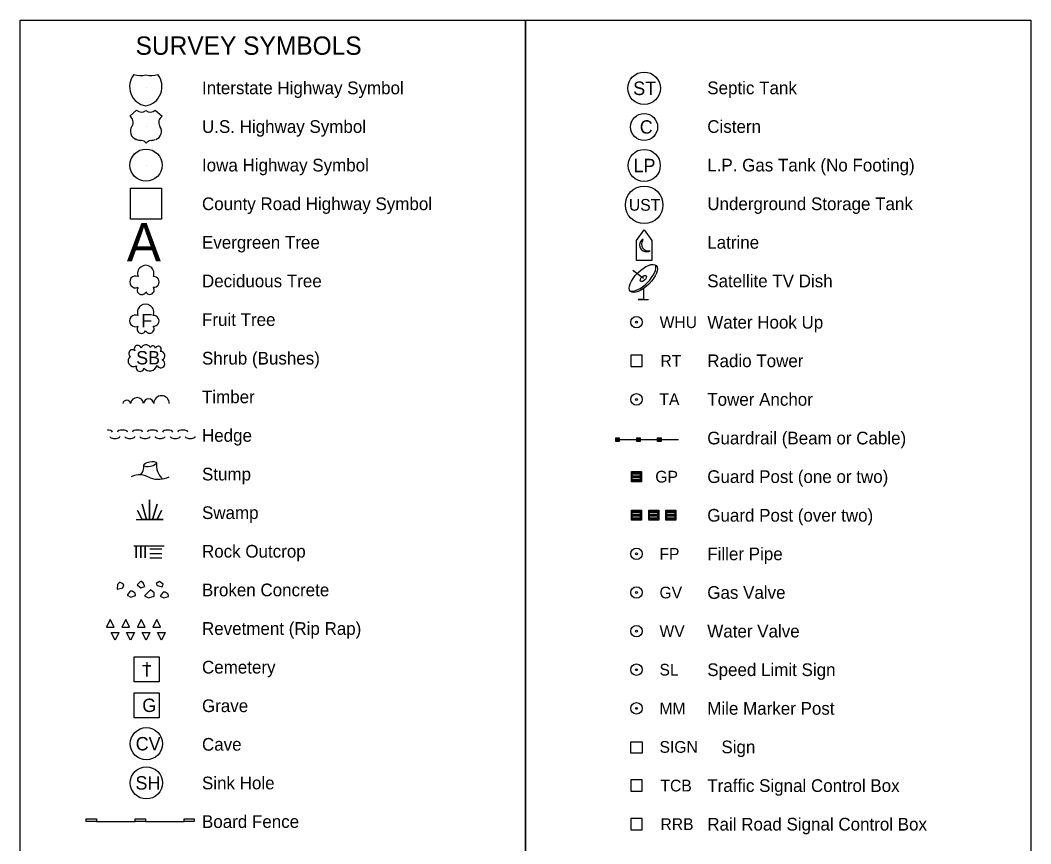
# Model space of a CAD drawing. Extents: x 6082259 to 6083454, y 5964102 to 5966092.
# Drawn here: x 6082259 to 6083454, y 5965119 to 5966092 of the extents above; entities that cross this region are included whole.
import ezdxf

# ---------------------------------------------------------------- set-up
doc = ezdxf.new("R2010")
doc.units = 0
for name, color, linetype in [('Default', 7, 'Continuous'), ('dsnCellElements', 7, 'Continuous'), ('SheetBorder', 7, 'Continuous'), ('Text', 7, 'Continuous')]:
    doc.layers.add(name, color=color, linetype=linetype)

msp = doc.modelspace()

# ---------------------------------------------------------------- linework, layer by layer
at = {"layer": 'Default'}
for points in [[(6082259, 5966092.2), (6082856.5, 5966092.2), (6082856.5, 5964102.2), (6082259, 5964102.2)], [(6082856.5, 5966092.2), (6083454, 5966092.2), (6083454, 5964102.2), (6082856.5, 5964102.2)]]:
    msp.add_lwpolyline(points, close=True, dxfattribs=at)
at = {"layer": 'dsnCellElements'}
for p, q in [((6082407.8, 5966012.2), (6082407.8, 5966012.2)), ((6082388.5, 5965978.8), (6082396.6, 5965986)), ((6082418.8, 5965985.9), (6082426.9, 5965978.7)), ((6082391, 5965966.7), (6082391.4, 5965967.3)), ((6082407.8, 5965966.5), (6082407.8, 5965966.5)), ((6082396.7, 5965951), (6082396, 5965951.3)), ((6082402.5, 5965950.1), (6082401.5, 5965950.1)), ((6082407.8, 5965920.9), (6082407.8, 5965920.9)), ((6082995.9, 5965786.9), (6082983.5, 5965796.2)), ((6082412.3, 5965467.3), (6082426.5, 5965467.3)), ((6082412.3, 5965462), (6082426.5, 5965462)), ((6082412.3, 5965456.6), (6082426.5, 5965456.6))]:
    msp.add_line(p, q, dxfattribs=at)
for points in [[(6082389.5, 5965893.5), (6082426, 5965893.5), (6082426, 5965857), (6082389.5, 5965857), (6082389.5, 5965893.5)], [(6082987.8, 5965808.3), (6082987.8, 5965831.8), (6082996.9, 5965844.5), (6083005.9, 5965831.8), (6083005.9, 5965808.3), (6082987.8, 5965808.3)], [(6082995.9, 5965774.5), (6082995.9, 5965762.1), (6082989.7, 5965762.1), (6083002.1, 5965762.1)], [(6082987.8, 5965682.8), (6082987.8, 5965682.8), (6082994.6, 5965682.8), (6082994.6, 5965696.4), (6082981, 5965696.4), (6082981, 5965682.8), (6082987.8, 5965682.8)], [(6082963.2, 5965594.3), (6082963.2, 5965598.4), (6082967.3, 5965598.4), (6082967.3, 5965594.3), (6082963.2, 5965594.3), (6082963.2, 5965595.7), (6082967.3, 5965595.7), (6082967.3, 5965597), (6082963.2, 5965597)], [(6082963.2, 5965596.4), (6083037.5, 5965596.4)], [(6082988, 5965594.3), (6082988, 5965598.4), (6082992.1, 5965598.4), (6082992.1, 5965594.3), (6082988, 5965594.3), (6082988, 5965595.7), (6082992.1, 5965595.7), (6082992.1, 5965597), (6082988, 5965597)], [(6083012.7, 5965594.3), (6083012.7, 5965598.4), (6083016.9, 5965598.4), (6083016.9, 5965594.3), (6083012.7, 5965594.3), (6083012.7, 5965595.7), (6083016.9, 5965595.7), (6083016.9, 5965597), (6083012.7, 5965597)], [(6082982.8, 5965547.7), (6082982.8, 5965557.6), (6082992.7, 5965557.6), (6082992.7, 5965547.7), (6082982.8, 5965547.7), (6082982.8, 5965549.7), (6082992.7, 5965549.7), (6082992.7, 5965551.7), (6082982.8, 5965551.7), (6082982.8, 5965553.7), (6082992.7, 5965553.7), (6082992.7, 5965555.6), (6082982.8, 5965555.6)], [(6082396, 5965502.1), (6082428.1, 5965502.1), (6082421, 5965502.1), (6082426.3, 5965512.8), (6082421, 5965502.1), (6082415.6, 5965502.1), (6082421, 5965520), (6082415.6, 5965502.1), (6082412.1, 5965502.1), (6082412.1, 5965525.3), (6082412.1, 5965502.1), (6082408.5, 5965502.1), (6082403.2, 5965520), (6082408.5, 5965502.1), (6082403.2, 5965502.1), (6082397.8, 5965512.8), (6082403.2, 5965502.1)], [(6082982.8, 5965502.1), (6082982.8, 5965512), (6082992.7, 5965512), (6082992.7, 5965502.1), (6082982.8, 5965502.1), (6082982.8, 5965504.1), (6082992.7, 5965504.1), (6082992.7, 5965506), (6082982.8, 5965506), (6082982.8, 5965508), (6082992.7, 5965508), (6082992.7, 5965510), (6082982.8, 5965510)], [(6083003.2, 5965502.1), (6083003.2, 5965512), (6083013.1, 5965512), (6083013.1, 5965502.1), (6083003.2, 5965502.1), (6083003.2, 5965504.1), (6083013.1, 5965504.1), (6083013.1, 5965506), (6083003.2, 5965506), (6083003.2, 5965508), (6083013.1, 5965508), (6083013.1, 5965510), (6083003.2, 5965510)], [(6083023.5, 5965502.1), (6083023.5, 5965512), (6083033.4, 5965512), (6083033.4, 5965502.1), (6083023.5, 5965502.1), (6083023.5, 5965504.1), (6083033.4, 5965504.1), (6083033.4, 5965506), (6083023.5, 5965506), (6083023.5, 5965508), (6083033.4, 5965508), (6083033.4, 5965510), (6083023.5, 5965510)], [(6082393.5, 5965470.9), (6082396.2, 5965470.9), (6082396.2, 5965456.6), (6082396.2, 5965470.9), (6082401.6, 5965470.9), (6082401.6, 5965456.6), (6082401.6, 5965470.9), (6082406.9, 5965470.9), (6082406.9, 5965456.6), (6082406.9, 5965470.9), (6082429.2, 5965470.9)], [(6082361, 5965374.6), (6082370.2, 5965374.6), (6082365.6, 5965383.8), (6082361, 5965374.6)], [(6082379.3, 5965374.6), (6082388.4, 5965374.6), (6082383.9, 5965383.8), (6082379.3, 5965374.6)], [(6082397.6, 5965374.6), (6082406.7, 5965374.6), (6082402.1, 5965383.8), (6082397.6, 5965374.6)], [(6082415.8, 5965374.6), (6082424.9, 5965374.6), (6082420.4, 5965383.8), (6082415.8, 5965374.6)], [(6082366.7, 5965368.6), (6082375.8, 5965368.6), (6082371.2, 5965359.5), (6082366.7, 5965368.6)], [(6082384.9, 5965368.6), (6082394.1, 5965368.6), (6082389.5, 5965359.5), (6082384.9, 5965368.6)], [(6082403.2, 5965368.6), (6082412.3, 5965368.6), (6082407.8, 5965359.5), (6082403.2, 5965368.6)], [(6082421.5, 5965368.6), (6082430.6, 5965368.6), (6082426, 5965359.5), (6082421.5, 5965368.6)], [(6082393.8, 5965310.2), (6082393.8, 5965339.7), (6082423.4, 5965339.7), (6082423.4, 5965310.2), (6082393.8, 5965310.2)], [(6082408.6, 5965333.3), (6082408.6, 5965316.6), (6082408.6, 5965328.9), (6082413.5, 5965328.9), (6082403.7, 5965328.9)], [(6082987.8, 5965180.8), (6082987.8, 5965180.8), (6082994.6, 5965180.8), (6082994.6, 5965194.3), (6082981, 5965194.3), (6082981, 5965180.8), (6082987.8, 5965180.8)], [(6082349.4, 5965145), (6082395, 5965145)], [(6082407.2, 5965145), (6082452.8, 5965145)], [(6082464.9, 5965145), (6082464.9, 5965145)], [(6082987.8, 5965135.1), (6082987.8, 5965135.1), (6082994.6, 5965135.1), (6082994.6, 5965148.7), (6082981, 5965148.7), (6082981, 5965135.1), (6082987.8, 5965135.1)]]:
    msp.add_lwpolyline(points, dxfattribs=at)
for points in [[(6082981.8, 5965546.7), (6082981.8, 5965558.6), (6082993.7, 5965558.6), (6082993.7, 5965546.7)], [(6082981.8, 5965501.1), (6082981.8, 5965513), (6082993.7, 5965513), (6082993.7, 5965501.1)], [(6083002.2, 5965501.1), (6083002.2, 5965513), (6083014.1, 5965513), (6083014.1, 5965501.1)], [(6083022.5, 5965501.1), (6083022.5, 5965513), (6083034.4, 5965513), (6083034.4, 5965501.1)], [(6082401.7, 5965429), (6082397.3, 5965424.9), (6082401.5, 5965421.3), (6082406.4, 5965422.8), (6082404.3, 5965427.2)], [(6082423.7, 5965428.6), (6082419.9, 5965426.3), (6082421.1, 5965424.2), (6082427.1, 5965422.6), (6082427.9, 5965425.5)], [(6082376.8, 5965427.8), (6082374.2, 5965425.4), (6082373.7, 5965419.7), (6082380.2, 5965421.3), (6082381.5, 5965424.9), (6082379.7, 5965426.2)], [(6082389.2, 5965417.2), (6082385.6, 5965412.5), (6082389.8, 5965410.4), (6082395.5, 5965412.3), (6082394.9, 5965415.1), (6082391.3, 5965417.2)], [(6082413.2, 5965419), (6082406, 5965411.8), (6082410.9, 5965409.4), (6082417.4, 5965411.3), (6082417.6, 5965415.4)], [(6082428.2, 5965416), (6082424.6, 5965411.4), (6082428.7, 5965409.3), (6082434.4, 5965411.1), (6082433.9, 5965413.9), (6082430.3, 5965416)], [(6082393.7, 5965267.5), (6082393.7, 5965297.2), (6082423.5, 5965297.2), (6082423.5, 5965267.5)], [(6082981, 5965225.7), (6082981, 5965239.2), (6082994.6, 5965239.2), (6082994.6, 5965225.7)], [(6082337.2, 5965145), (6082337.2, 5965148.4), (6082349.4, 5965148.4), (6082349.4, 5965145)], [(6082395, 5965145), (6082395, 5965148.4), (6082407.2, 5965148.4), (6082407.2, 5965145)], [(6082452.8, 5965145), (6082452.8, 5965148.4), (6082464.9, 5965148.4), (6082464.9, 5965145)]]:
    msp.add_lwpolyline(points, close=True, dxfattribs=at)
for centre, radius in [((6082996.8, 5965966), 16), ((6082407.8, 5965920.9), 19), ((6082996.9, 5965920.5), 19), ((6082996.9, 5965873.9), 22.2), ((6082987.8, 5965735.2), 6.79), ((6082987.8, 5965735.2), 1.13), ((6082987.8, 5965644), 6.79), ((6082987.8, 5965644), 1.13), ((6082987.8, 5965461.4), 6.79), ((6082987.8, 5965461.4), 1.13), ((6082987.8, 5965415.8), 6.79), ((6082987.8, 5965415.8), 1.13), ((6082987.8, 5965370.1), 6.79), ((6082987.8, 5965370.1), 1.13), ((6082987.8, 5965324.5), 6.79), ((6082987.8, 5965324.5), 1.13), ((6082987.8, 5965278.8), 6.79), ((6082987.8, 5965278.8), 1.13), ((6082408.2, 5965237), 19), ((6082408.2, 5965190.7), 19)]:
    msp.add_circle(centre, radius, dxfattribs=at)
for centre, radius, start, end in [((6082411.4, 5966013.6), 23, 141.2897, 260.377), ((6082401.1, 5966050), 23.3, 250.8344, 286.0898), ((6082414, 5966050), 23.3, 253.9102, 289.1613), ((6082403.7, 5966013.6), 23, 279.623, 38.7204), ((6082414, 5966050), 23.3, 289.1818, 289.185), ((6082384.1, 5965971.6), 8.46, 328.1178, 58.4185), ((6082402.4, 5965992.1), 8.46, 226.652, 308.6604), ((6082413, 5965992.1), 8.46, 230.5703, 313.348), ((6082431.3, 5965971.5), 8.46, 121.5815, 211.8822), ((6082399.6, 5965961), 10.3, 145.8972, 250.3585), ((6082415.8, 5965960.9), 10.3, 289.6415, 34.1028), ((6082403.5, 5965974.1), 24.1, 253.4797, 265.7777), ((6082402.1, 5965943), 7.07, 33.6844, 87.4407), ((6082413.9, 5965942.9), 7.07, 95.8567, 146.3156), ((6082411.9, 5965974.1), 24.1, 274.6642, 286.5203), ((6082999.3, 5965826.4), 7.87, 116.2289, 304.7925), ((6083001.5, 5965827.5), 7.91, 142.8907, 286.2253), ((6082407.5, 5965792.7), 9.75, 338.2051, 201.7949), ((6082395.5, 5965782.8), 6.97, 65.4824, 294.5175), ((6082417, 5965782.8), 6.36, 265.9982, 94.0018), ((6082402.6, 5965773.2), 5.31, 142.7501, 335.3223), ((6082412.2, 5965773.4), 5.3, 206.5242, 35.4033), ((6082407.3, 5965746.8), 9.75, 338.2051, 201.7949), ((6082395.4, 5965736.8), 6.97, 65.4824, 294.5175), ((6082416.8, 5965736.8), 6.36, 265.9982, 94.0018), ((6082402.5, 5965727.3), 5.31, 142.7501, 335.3223), ((6082412.1, 5965727.4), 5.3, 206.5242, 35.4033), ((6082398.1, 5965703.7), 4.12, 10.5948, 214.3611), ((6082407.6, 5965703.1), 5.57, 22.6036, 165.7836), ((6082415.7, 5965704.1), 3.15, 0.4605, 158.7839), ((6082422.3, 5965703.3), 3.57, 311.3936, 166.4114), ((6082393.2, 5965689.4), 6.62, 125.8289, 299.2848), ((6082391.7, 5965698.3), 4.32, 45.3455, 236.8073), ((6082425, 5965695.5), 5.15, 290.9039, 94.3687), ((6082400.8, 5965681.8), 4.68, 157.0258, 349.7602), ((6082412.2, 5965686.7), 8.99, 220.0183, 343.6977), ((6082425.2, 5965686.2), 4.79, 204.8294, 69.8871), ((6082397.2, 5965638.4), 7.66, 5.6097, 174.3903), ((6082410.9, 5965638.4), 6.15, 6.8184, 173.1816), ((6082426.2, 5965639.2), 9.15, 0, 180), ((6082385, 5965638.5), 4.63, 8.8069, 171.1931), ((6082388.6, 5965565.5), 16.7, 319.4836, 1.8241), ((6082444, 5965567.1), 24, 175.4776, 225.2691), ((6082400.1, 5965530.5), 24.2, 58.6739, 113.6979), ((6082422.1, 5965578.6), 29, 251.1942, 296.4339)]:
    msp.add_arc(centre, radius, start, end, dxfattribs=at)
for centre, major_axis, ratio in [((6082995.9, 5965786.9), (-15.3, -15.3), 0.428571), ((6082995.9, 5965786.9), (-3.28, -3.28), 0.5), ((6082412.7, 5965567.5), (-7.43, -1.49), 0.385758)]:
    msp.add_ellipse(centre, major_axis=major_axis, ratio=ratio, dxfattribs=at)
for centre, major_axis, ratio, start_param, end_param in [((6082994.1, 5965788.6), (-15.3, -15.3), 0.428571, 0.159141, 2.993624), ((6082362.1, 5965605.4), (5.94, 0), 0.4, 0, 1.570796), ((6082379.9, 5965605.4), (-5.94, 0), 0.4, 4.712389, 6.283185), ((6082379.9, 5965605.4), (5.94, 0), 0.4, 0, 1.570796), ((6082397.7, 5965605.4), (-5.94, 0), 0.4, 4.712389, 6.283185), ((6082397.7, 5965605.4), (5.94, 0), 0.4, 0, 1.570796), ((6082415.5, 5965605.4), (-5.94, 0), 0.4, 4.712389, 6.283185), ((6082415.5, 5965605.4), (5.94, 0), 0.4, 0, 1.570796), ((6082433.4, 5965605.4), (-5.94, 0), 0.4, 4.712389, 6.283185), ((6082433.4, 5965605.4), (5.94, 0), 0.4, 0, 1.570796), ((6082451.2, 5965605.4), (-5.94, 0), 0.4, 4.712389, 6.283185), ((6082451.2, 5965605.4), (5.94, 0), 0.4, 0, 1.570796), ((6082371, 5965600.1), (-5.94, 0), 0.4, 0, 3.141593), ((6082388.8, 5965600.1), (-5.94, 0), 0.4, 0, 3.141593), ((6082406.6, 5965600.1), (-5.94, 0), 0.4, 0, 3.141593), ((6082424.5, 5965600.1), (-5.94, 0), 0.4, 0, 3.141593), ((6082442.3, 5965600.1), (-5.94, 0), 0.4, 0, 3.141593), ((6082460.1, 5965600.1), (-5.94, 0), 0.4, 0, 3.141593)]:
    msp.add_ellipse(centre, major_axis=major_axis, ratio=ratio, start_param=start_param, end_param=end_param, dxfattribs=at)
at = {"layer": 'Text'}
msp.add_circle((6082996.8, 5966011.7), 19.2, dxfattribs=at)

# ---------------------------------------------------------------- texts
at = {"layer": 'dsnCellElements'}
for s, height, p in [('C', 15.8, (6082991.7, 5965958.1)), ('LP', 15.85, (6082984.3, 5965912.5)), ('UST', 13.87, (6082978.8, 5965867)), ('A', 45.3, (6082385.1, 5965807)), ('F', 15.8, (6082402.3, 5965729.3)), ('WHU', 13.82, (6083015.2, 5965728.3)), ('SB', 15.85, (6082396.1, 5965685.3)), ('RT', 13.87, (6083016.1, 5965682.7)), ('TA', 13.93, (6083014.8, 5965637.2)), ('GP', 13.87, (6083010, 5965545.7)), ('FP', 13.82, (6083015, 5965454.5)), ('GV', 13.82, (6083015, 5965408.8)), ('WV', 13.82, (6083015, 5965363.2)), ('SL', 13.82, (6083015, 5965317.6)), ('G', 15.8, (6082403.4, 5965274.5)), ('MM', 13.82, (6083015, 5965271.9)), ('CV', 15.85, (6082395.6, 5965229.1)), ('Cave', 15, (6082474, 5965228.8)), ('SIGN', 13.87, (6083015, 5965226.3)), ('Sign', 15, (6083088.2, 5965225.7)), ('SH', 15.85, (6082395.3, 5965182.8)), ('TCB', 13.87, (6083016.1, 5965180.6)), ('RRB', 13.87, (6083016.1, 5965135))]:
    msp.add_text(s, height=height, dxfattribs=at).set_placement(p)
at = {"layer": 'SheetBorder'}
for s, height, p in [('SURVEY SYMBOLS', 21.667, (6082395.5, 5966051.3)), ('Interstate Highway Symbol', 15, (6082474, 5966004.7)), ('Septic Tank', 15, (6083071.5, 5966004.7)), ('U.S. Highway Symbol', 15, (6082474, 5965959)), ('Cistern', 15, (6083071.5, 5965959)), ('Iowa Highway Symbol', 15, (6082474, 5965913.4)), ('L.P. Gas Tank (No Footing)', 15, (6083071.5, 5965913.4)), ('County Road Highway Symbol', 15, (6082474, 5965867.7)), ('Underground Storage Tank', 15, (6083071.5, 5965867.7)), ('Evergreen Tree', 15, (6082474, 5965822.1)), ('Latrine', 15, (6083071.5, 5965822.1)), ('Deciduous Tree', 15, (6082474, 5965776.5)), ('Satellite TV Dish', 15, (6083071.5, 5965776.5)), ('Fruit Tree', 15, (6082474, 5965730.8)), ('Water Hook Up', 15, (6083071.5, 5965727.7)), ('Shrub (Bushes)', 15, (6082474, 5965685.2)), ('Radio Tower', 15, (6083071.5, 5965682.1)), ('Timber', 15, (6082474, 5965639.5)), ('Tower Anchor', 15, (6083071.5, 5965636.5)), ('Hedge', 15, (6082474, 5965593.9)), ('Guardrail (Beam or Cable)', 15, (6083071.5, 5965590.8)), ('Stump', 15, (6082474, 5965548.2)), ('Guard Post (one or two)', 15, (6083071.5, 5965545.2)), ('Swamp', 15, (6082474, 5965502.6)), ('Guard Post (over two)', 15, (6083071.5, 5965499.5)), ('Rock Outcrop', 15, (6082474, 5965457)), ('Filler Pipe', 15, (6083071.5, 5965453.9)), ('Broken Concrete', 15, (6082474, 5965411.3)), ('Gas Valve', 15, (6083071.5, 5965408.3)), ('Revetment (Rip Rap)', 15, (6082474, 5965365.7)), ('Water Valve', 15, (6083071.5, 5965362.6)), ('Cemetery', 15, (6082474, 5965320)), ('Speed Limit Sign', 15, (6083071.5, 5965317)), ('Grave', 15, (6082474, 5965274.4)), ('Mile Marker Post', 15, (6083071.5, 5965271.3)), ('Sink Hole', 15, (6082474, 5965183.1)), ('Traffic Signal Control Box', 15, (6083071.5, 5965180)), ('Board Fence', 15, (6082474, 5965137.5)), ('Rail Road Signal Control Box', 15, (6083071.5, 5965134.4))]:
    msp.add_text(s, height=height, dxfattribs=at).set_placement(p)
at = {"layer": 'Text'}
msp.add_text('ST', height=15.99, dxfattribs=at).set_placement((6082983.8, 5966003.7))

doc.saveas('drawing.dxf')
